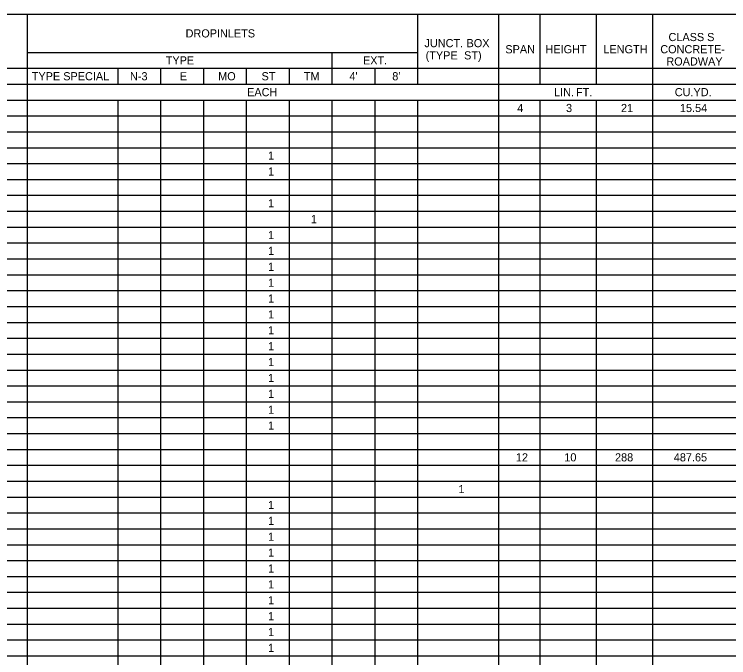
# Model space of a CAD drawing. Extents: x 1226564 to 1228153, y 151309 to 152340.
# Drawn here: x 1227436.4 to 1227810.6, y 151823.8 to 152160.5 of the extents above; entities that cross this region are included whole.
import ezdxf

# ---------------------------------------------------------------- set-up
doc = ezdxf.new("R2010")
doc.units = 0
doc.layers.add('R_Dimension', color=7, linetype='Continuous')

msp = doc.modelspace()

# ---------------------------------------------------------------- linework, layer by layer
at = {"layer": 'R_Dimension'}
for p, q in [((1226563.55, 152160.49), (1228152.75, 152160.49)), ((1227443.42, 151354.44), (1227443.42, 152160.49)), ((1227647.84, 152123.93), (1227647.84, 152160.49)), ((1227690.22, 151354.44), (1227690.22, 152160.49)), ((1227711.83, 152123.93), (1227711.83, 152160.49)), ((1227741.33, 152123.93), (1227741.33, 152160.49)), ((1227770.83, 151354.44), (1227770.83, 152160.49)), ((1227443.42, 152140.55), (1227647.84, 152140.55)), ((1227602.97, 152123.93), (1227602.97, 152140.55)), ((1227254.62, 152132.24), (1227961.95, 152132.24)), ((1227490.79, 152123.93), (1227490.79, 152132.24)), ((1227513.22, 152123.93), (1227513.22, 152132.24)), ((1227535.66, 152123.93), (1227535.66, 152132.24)), ((1227558.1, 152123.93), (1227558.1, 152132.24)), ((1227580.53, 152123.93), (1227580.53, 152132.24)), ((1227625.41, 152123.93), (1227625.41, 152132.24)), ((1226840.79, 152123.93), (1228152.75, 152123.93)), ((1227443.42, 152123.93), (1227961.95, 152123.93)), ((1226563.55, 152115.62), (1228152.75, 152115.62)), ((1227490.79, 151354.44), (1227490.79, 152115.62)), ((1227513.22, 151354.44), (1227513.22, 152115.62)), ((1227535.66, 151354.44), (1227535.66, 152115.62)), ((1227558.1, 151354.44), (1227558.1, 152115.62)), ((1227580.53, 151354.44), (1227580.53, 152115.62)), ((1227602.97, 151354.44), (1227602.97, 152115.62)), ((1227625.41, 151354.44), (1227625.41, 152115.62)), ((1227647.84, 151354.44), (1227647.84, 152115.62)), ((1227711.83, 151354.44), (1227711.83, 152115.62)), ((1227741.33, 151354.44), (1227741.33, 152115.62)), ((1226563.55, 152107.31), (1228152.75, 152107.31)), ((1226563.55, 152099), (1228152.75, 152099)), ((1226563.55, 152090.69), (1228152.75, 152090.69)), ((1226563.55, 152082.38), (1228152.75, 152082.38)), ((1226563.55, 152074.07), (1228152.75, 152074.07)), ((1226563.55, 152065.76), (1228152.75, 152065.76)), ((1226563.55, 152057.45), (1228152.75, 152057.45)), ((1226563.55, 152049.14), (1228152.75, 152049.14)), ((1226563.55, 152040.83), (1228152.75, 152040.83)), ((1226563.55, 152032.52), (1228152.75, 152032.52)), ((1226563.55, 152024.21), (1228152.75, 152024.21)), ((1226563.55, 152015.9), (1228152.75, 152015.9)), ((1226563.55, 152007.59), (1228152.75, 152007.59)), ((1226563.55, 151999.28), (1228152.75, 151999.28)), ((1226563.55, 151990.97), (1228152.75, 151990.97)), ((1226563.55, 151982.66), (1228152.75, 151982.66)), ((1226563.55, 151974.35), (1228152.75, 151974.35)), ((1226563.55, 151966.04), (1228152.75, 151966.04)), ((1226563.55, 151957.73), (1228152.75, 151957.73)), ((1226563.55, 151949.42), (1228152.75, 151949.42)), ((1226563.55, 151941.11), (1228152.75, 151941.11)), ((1226563.55, 151932.8), (1228152.75, 151932.8)), ((1226563.55, 151924.49), (1228152.75, 151924.49)), ((1226563.55, 151916.18), (1228152.75, 151916.18)), ((1226563.55, 151907.87), (1228152.75, 151907.87)), ((1226563.55, 151899.56), (1228152.75, 151899.56)), ((1226563.55, 151891.25), (1228152.75, 151891.25)), ((1226563.55, 151882.94), (1228152.75, 151882.94)), ((1226563.55, 151874.64), (1228152.75, 151874.64)), ((1226563.55, 151866.33), (1228152.75, 151866.33)), ((1226563.55, 151858.02), (1228152.75, 151858.02)), ((1226563.55, 151849.71), (1228152.75, 151849.71)), ((1226563.55, 151841.4), (1228152.75, 151841.4)), ((1226563.55, 151833.09), (1228152.75, 151833.09)), ((1226563.55, 151824.78), (1228152.75, 151824.78))]:
    msp.add_line(p, q, dxfattribs=at)

# ---------------------------------------------------------------- texts
for s, height, p in [('DROP', 4.261, (1227526.14, 152148.39)), (' INLETS', 4.261, (1227541, 152148.39)), ('CLASS', 4.261, (1227779.04, 152146.47)), (' S', 4.261, (1227797.7, 152146.47)), ('JUNCT.', 4.261, (1227651.23, 152143.28)), (' BOX', 4.261, (1227671.7, 152143.28)), ('SPAN', 4.261, (1227693.59, 152140.08)), ('HEIGHT', 4.261, (1227714.6, 152140.08)), ('LENGTH', 4.261, (1227744.94, 152140.08)), ('CONCRETE-', 4.261, (1227774.73, 152140.08)), ('(TYPE', 4.261, (1227651.85, 152136.88)), ('  ST)', 4.261, (1227668.83, 152136.88)), ('TYPE', 4.261, (1227515.74, 152134.26)), ('EXT.', 4.261, (1227619.03, 152134.26)), ('ROADWAY', 4.261, (1227777.92, 152133.69)), ('TYPE', 4.261, (1227445.58, 152125.95)), (' SPECIAL', 4.261, (1227460.48, 152125.95)), ('N-3', 4.261, (1227497.04, 152125.95)), ('E', 4.26, (1227523.13, 152125.95)), ('MO', 4.261, (1227543.2, 152125.95)), ('ST', 4.261, (1227565.91, 152125.95)), ('TM', 4.261, (1227588.09, 152125.95)), ("4'", 4.261, (1227611.94, 152125.95)), ("8'", 4.261, (1227634.38, 152125.95)), ('EACH', 4.261, (1227558.36, 152117.64)), ('LIN.', 4.261, (1227719.1, 152117.64)), (' FT.', 4.261, (1227729.03, 152117.64)), ('CU.YD.', 4.261, (1227782.31, 152117.64)), ('4', 4.26, (1227699.82, 152109.33)), ('3', 4.26, (1227725.37, 152109.33)), ('21', 4.261, (1227754.16, 152109.33)), ('15.54', 4.261, (1227785.03, 152109.33)), ('1', 4.26, (1227569.31, 152084.41)), ('1', 4.26, (1227569.31, 152076.1)), ('1', 4.26, (1227569.31, 152059.48)), ('1', 4.26, (1227591.75, 152051.17)), ('1', 4.26, (1227569.31, 152042.86)), ('1', 4.26, (1227569.31, 152034.55)), ('1', 4.26, (1227569.31, 152026.24)), ('1', 4.26, (1227569.31, 152017.93)), ('1', 4.26, (1227569.31, 152009.62)), ('1', 4.26, (1227569.31, 152001.31)), ('1', 4.26, (1227569.31, 151993)), ('1', 4.26, (1227569.31, 151984.69)), ('1', 4.26, (1227569.31, 151976.38)), ('1', 4.26, (1227569.31, 151968.07)), ('1', 4.26, (1227569.31, 151959.76)), ('1', 4.26, (1227569.31, 151951.45)), ('1', 4.26, (1227569.31, 151943.14)), ('12', 4.261, (1227699.11, 151926.52)), ('10', 4.261, (1227724.48, 151926.52)), ('288', 4.261, (1227751.04, 151926.52)), ('487.65', 4.261, (1227781.81, 151926.52)), ('1', 4.26, (1227669.03, 151909.9)), ('1', 4.26, (1227569.31, 151901.59)), ('1', 4.26, (1227569.31, 151893.28)), ('1', 4.26, (1227569.31, 151884.97)), ('1', 4.26, (1227569.31, 151876.66)), ('1', 4.26, (1227569.31, 151868.35)), ('1', 4.26, (1227569.31, 151860.04)), ('1', 4.26, (1227569.31, 151851.73)), ('1', 4.26, (1227569.31, 151843.42)), ('1', 4.26, (1227569.31, 151835.11)), ('1', 4.26, (1227569.31, 151826.8))]:
    msp.add_text(s, height=height, dxfattribs=at).set_placement(p)

doc.saveas('drawing.dxf')
